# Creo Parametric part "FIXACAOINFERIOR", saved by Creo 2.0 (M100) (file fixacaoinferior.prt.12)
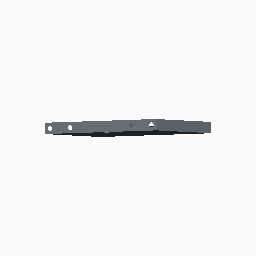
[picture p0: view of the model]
Units: millimeter Newton Second (mmNs); MM, TONNE, SECS

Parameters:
  PTC_COMMON_NAME = "fixacaoinferior.prt"
  METRIC = "YES"

Other parameters: DRILL_POINT_ANGLE, DRILL_DEPTH, DRILL_DIAMETER, THREAD_DIAMETER, THREADS_PER_INCH, THREAD_DEPTH

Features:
  1. datum plane "RIGHT"
  2. datum plane "TOP"
  3. datum plane "FRONT"
  4. coordinate system
  5. protrusion "Section 1"
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
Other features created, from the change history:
  sketch "Sketch 1"
  extruded cut "Extrude 5"
  sketch "Sketch 2"
  extruded cut "Extrude 6"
